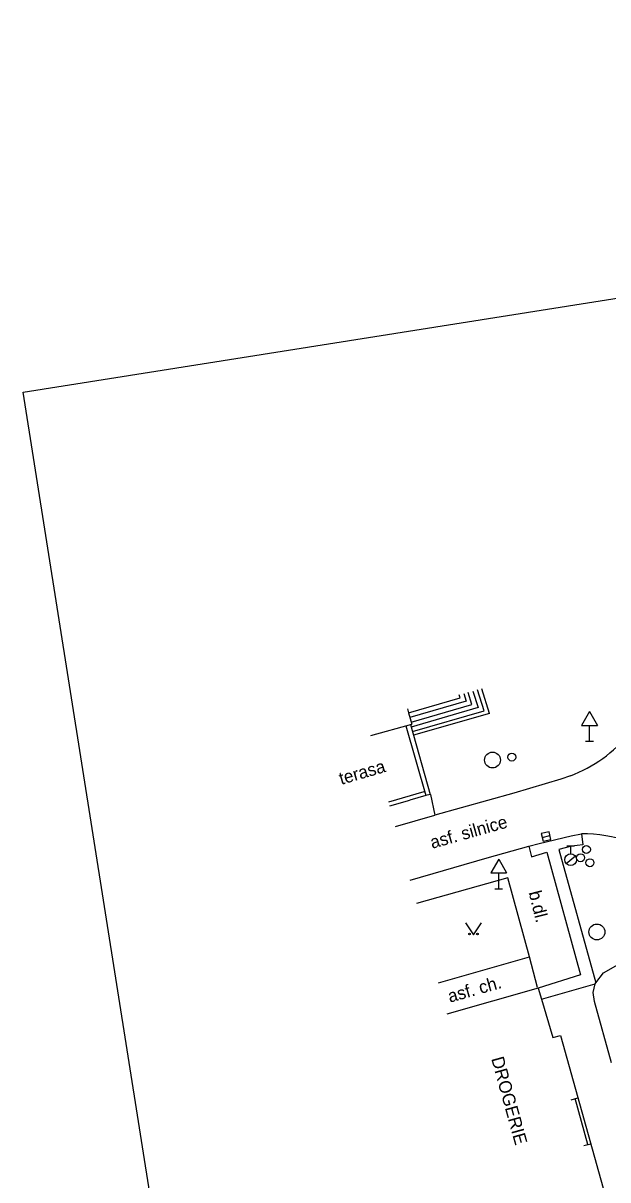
# Model space of a CAD drawing. Extents: x -599098 to -598820, y -1159597 to -1158744.
# Drawn here: x -599097.9 to -599061.1, y -1158817.2 to -1158744.4 of the extents above; entities that cross this region are included whole.
import ezdxf

# ---------------------------------------------------------------- set-up
doc = ezdxf.new("R2010")
doc.units = 0
for name, color, linetype in [('budovy', 7, 'Continuous'), ('dopravní značky semafory', 7, 'Continuous'), ('druh pozemku stromy', 7, 'Continuous'), ('kresba', 7, 'Continuous'), ('mapový rám legenda', 7, 'Continuous'), ('popisy', 7, 'Continuous'), ('značky IS', 7, 'Continuous')]:
    doc.layers.add(name, color=color, linetype=linetype)

msp = doc.modelspace()

# ---------------------------------------------------------------- linework, layer by layer
at = {"layer": 'budovy'}
for p, q in [((-599073.708, -1158787.532), (-599073.63, -1158787.8)), ((-599076.014, -1158789.22), (-599073.43, -1158788.5)), ((-599073.63, -1158787.8), (-599073.43, -1158788.5)), ((-599065.48, -1158805.11), (-599071.218, -1158806.747)), ((-599065.48, -1158805.11), (-599065.27, -1158805.8)), ((-599065.27, -1158805.8), (-599064.56, -1158808.22)), ((-599064.56, -1158808.22), (-599064.06, -1158808.09)), ((-599064.06, -1158808.09), (-599061.14, -1158818.6))]:
    msp.add_line(p, q, dxfattribs=at)
at = {"layer": 'dopravní značky semafory'}
for p, q in [((-599062.25, -1158787.714), (-599062.75, -1158788.58)), ((-599062.25, -1158787.714), (-599061.75, -1158788.58)), ((-599062.75, -1158788.58), (-599061.75, -1158788.58)), ((-599062.25, -1158789.58), (-599062.25, -1158788.58)), ((-599062.5, -1158789.58), (-599062, -1158789.58)), ((-599067.96, -1158796.994), (-599068.46, -1158797.86)), ((-599067.96, -1158796.994), (-599067.46, -1158797.86)), ((-599068.46, -1158797.86), (-599067.46, -1158797.86)), ((-599067.96, -1158798.86), (-599067.96, -1158797.86)), ((-599068.21, -1158798.86), (-599067.71, -1158798.86))]:
    msp.add_line(p, q, dxfattribs=at)
at = {"layer": 'druh pozemku stromy'}
msp.add_lwpolyline([(-599070.046, -1158801.011), (-599069.546, -1158801.761), (-599069.046, -1158801.011)], dxfattribs=at)
for centre in [(-599069.796, -1158801.711), (-599069.296, -1158801.711)]:
    msp.add_circle(centre, 0.05, dxfattribs=at)
at = {"layer": 'kresba'}
for p, q in [((-599068.535, -1158787.84), (-599069.02, -1158786.27)), ((-599073.63, -1158787.8), (-599070.39, -1158786.85)), ((-599070.01, -1158787.06), (-599073.55, -1158788.08)), ((-599070.39, -1158786.85), (-599070.451, -1158786.656)), ((-599070.162, -1158786.578), (-599070.01, -1158787.06)), ((-599069.64, -1158787.26), (-599069.878, -1158786.501)), ((-599069.584, -1158786.422), (-599069.26, -1158787.46)), ((-599068.88, -1158787.66), (-599069.293, -1158786.344)), ((-599073.47, -1158788.37), (-599069.64, -1158787.26)), ((-599069.26, -1158787.46), (-599073.46, -1158788.69)), ((-599073.38, -1158788.97), (-599068.88, -1158787.66)), ((-599068.535, -1158787.84), (-599073.324, -1158789.188)), ((-599073.8, -1158788.603), (-599072.552, -1158793.002)), ((-599073.512, -1158788.523), (-599072.264, -1158792.92)), ((-599064.04, -1158791.97), (-599067.01, -1158792.85)), ((-599063.45, -1158791.75), (-599064.04, -1158791.97)), ((-599074.876, -1158793.381), (-599072.64, -1158792.73)), ((-599067.01, -1158792.85), (-599071.97, -1158794.23)), ((-599074.806, -1158793.635), (-599073.553, -1158793.277)), ((-599072.552, -1158793.002), (-599073.553, -1158793.277)), ((-599072.273, -1158792.927), (-599072.552, -1158793.002)), ((-599072.26, -1158792.92), (-599071.97, -1158794.23)), ((-599074.45, -1158794.937), (-599071.97, -1158794.23)), ((-599065.42, -1158796.01), (-599063.39, -1158795.54)), ((-599063.39, -1158795.54), (-599062.75, -1158795.4)), ((-599062.75, -1158795.4), (-599062.67, -1158796.1)), ((-599068.68, -1158796.919), (-599066.07, -1158796.18)), ((-599066.07, -1158796.18), (-599065.42, -1158796.01)), ((-599066.06, -1158796.19), (-599065.9, -1158796.86)), ((-599063.38, -1158796.19), (-599064.18, -1158796.38)), ((-599064.18, -1158796.38), (-599061.85, -1158804.77)), ((-599062.67, -1158796.1), (-599063.38, -1158796.19)), ((-599073.526, -1158798.314), (-599068.68, -1158796.919)), ((-599065.9, -1158796.86), (-599064.94, -1158796.55)), ((-599064.94, -1158796.55), (-599062.82, -1158804.27)), ((-599067.39, -1158798.18), (-599073.121, -1158799.794)), ((-599066.03, -1158803.15), (-599067.39, -1158798.18)), ((-599071.757, -1158804.777), (-599066.03, -1158803.15)), ((-599065.52, -1158805.08), (-599066.03, -1158803.15)), ((-599061.37, -1158804.16), (-599060.139, -1158803.454)), ((-599062.82, -1158804.27), (-599065.48, -1158805.11)), ((-599061.85, -1158804.77), (-599061.37, -1158804.16)), ((-599065.27, -1158805.8), (-599061.89, -1158804.85)), ((-599062.02, -1158805.38), (-599061.89, -1158804.85)), ((-599061.89, -1158804.85), (-599061.85, -1158804.77)), ((-599061.93, -1158805.96), (-599062.02, -1158805.38)), ((-599060.87, -1158809.81), (-599061.93, -1158805.96)), ((-599063.397, -1158812.133), (-599062.97, -1158812.014)), ((-599062.351, -1158814.956), (-599063.156, -1158812.066)), ((-599062.592, -1158815.023), (-599062.167, -1158814.905))]:
    msp.add_line(p, q, dxfattribs=at)
for centre, radius, start, end in [((-599066.559, -1158783.471), 8.843, 290.58137, 320.55224), ((-599062.785, -1158804.975), 9.575, 53.27848, 89.79121)]:
    msp.add_arc(centre, radius, start, end, dxfattribs=at)
at = {"layer": 'mapový rám legenda'}
for p, q in [((-599097.883, -1158767.619), (-598951.211, -1158744.389)), ((-599081.457, -1158871.327), (-599097.883, -1158767.619))]:
    msp.add_line(p, q, dxfattribs=at)
at = {"layer": 'značky IS'}
for p, q in [((-599065.224, -1158795.625), (-599064.736, -1158795.515)), ((-599063.68, -1158796.155), (-599063.18, -1158796.155)), ((-599063.43, -1158796.655), (-599063.43, -1158796.155)), ((-599063.724, -1158797.261), (-599063.134, -1158796.798))]:
    msp.add_line(p, q, dxfattribs=at)
msp.add_lwpolyline([(-599065.169, -1158795.87), (-599064.681, -1158795.76), (-599064.791, -1158795.271), (-599065.279, -1158795.381)], close=True, dxfattribs=at)
for centre, radius in [((-599068.35, -1158790.76), 0.5), ((-599067.134, -1158790.577), 0.25), ((-599062.44, -1158796.39), 0.25), ((-599063.43, -1158797.03), 0.375), ((-599062.81, -1158796.91), 0.25), ((-599062.22, -1158797.22), 0.25), ((-599061.78, -1158801.58), 0.5)]:
    msp.add_circle(centre, radius, dxfattribs=at)

# ---------------------------------------------------------------- texts
at = {"layer": 'popisy'}
for s, rotation, p in [('terasa', 16.23395, (-599077.871, -1158792.326)), ('asf. silnice', 15.75229, (-599072.145, -1158796.349)), ('b.dl.', 284.13093, (-599066.084, -1158799.09)), ('asf. ch.', 15.86071, (-599071.032, -1158806.035)), ('DROGERIE', 285.52692, (-599068.437, -1158809.548))]:
    msp.add_text(s, height=0.8, rotation=rotation, dxfattribs=at).set_placement(p)

doc.saveas('drawing.dxf')
